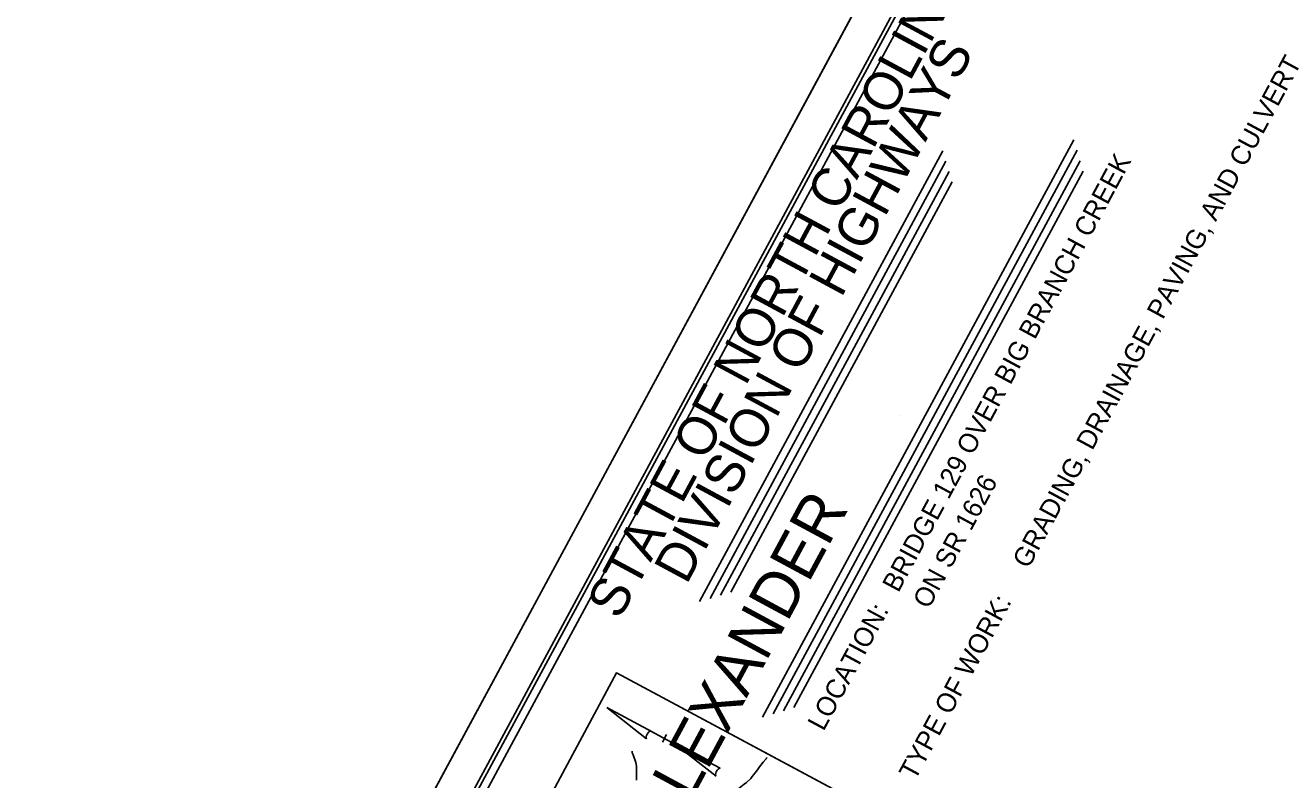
# Model space of a CAD drawing. Extents: x 1376167 to 1379209, y 761324 to 763997.
# Drawn here: x 1376167 to 1376982, y 763015 to 763505 of the extents above; entities that cross this region are included whole.
import ezdxf

# ---------------------------------------------------------------- set-up
doc = ezdxf.new("R2010")
doc.units = 0
for name, color, linetype in [('Default', 7, 'Continuous'), ('Old_Level_1', 7, 'Continuous'), ('Prop North Arrow for Plan Sheets CELL', 7, 'Continuous'), ('Sheet Cutting Line CELL', 7, 'Continuous'), ('Sheet Data Field CELL', 7, 'Continuous'), ('Sheet Plot Border Inside CELL', 7, 'Continuous'), ('Sheet Plot Border Outside CELL', 7, 'Continuous'), ('Sheet Title CELL', 7, 'Continuous'), ('Sheet Title Data Points CELL', 7, 'Continuous')]:
    doc.layers.add(name, color=color, linetype=linetype)

msp = doc.modelspace()

# ---------------------------------------------------------------- linework, layer by layer
at = {"layer": 'Default'}
for points in [[(1376563.93, 763014.38), (1376563.87, 763014.67), (1376563.82, 763014.91), (1376563.89, 763015.39), (1376563.85, 763015.89), (1376563.9, 763016.29), (1376563.89, 763017.05), (1376563.93, 763018.96), (1376563.99, 763020.92), (1376564.01, 763023.25), (1376563.78, 763024.72), (1376563.56, 763025.79), (1376561.67, 763030.75), (1376561.15, 763032.22), (1376561.1, 763032.48), (1376561.08, 763033.15)], [(1376648.76, 763029.08), (1376648.29, 763028.55), (1376648, 763028.24), (1376647.83, 763028.06), (1376646.1, 763025.98), (1376643.79, 763022.92), (1376642.92, 763021.74), (1376641.74, 763020.29), (1376640.75, 763018.98), (1376640.14, 763018.1), (1376639.06, 763016.64), (1376638.1, 763015.54), (1376635.43, 763012.95), (1376633.91, 763011.77), (1376630.52, 763009.14), (1376629.15, 763008.11), (1376628.26, 763007.42), (1376627.71, 763006.98)]]:
    msp.add_lwpolyline(points, dxfattribs=at)
at = {"layer": 'Old_Level_1'}
for points in [[(1376622.61, 762553.05), (1376345.79, 762701.47), (1376550.88, 763083.99), (1376827.7, 762935.57)], [(1376345.79, 762701.47), (1376660.36, 762532.81), (1376865.45, 762915.33), (1376550.88, 763083.99)]]:
    msp.add_lwpolyline(points, close=True, dxfattribs=at)
at = {"layer": 'Prop North Arrow for Plan Sheets CELL'}
for p, q in [((1376544.62, 763061.56), (1376544.6, 763061.53)), ((1376544.62, 763061.56), (1376544.6, 763061.53)), ((1376570.39, 763041.21), (1376544.6, 763061.53)), ((1376544.62, 763061.56), (1376574, 763045.8)), ((1376589.25, 763037.63), (1376573.14, 763046.26)), ((1376574, 763045.8), (1376573.17, 763046.25)), ((1376580.8, 763038.99), (1376580.78, 763038.96)), ((1376581.97, 763041.17), (1376580.8, 763038.99)), ((1376580.81, 763039.02), (1376583.45, 763043.94)), ((1376589.25, 763037.63), (1376615.54, 763016.92)), ((1376618.19, 763022.15), (1376589.25, 763037.63))]:
    msp.add_line(p, q, dxfattribs=at)
for centre, start_param, end_param in [((1376572.06, 763043.59), 0.216388, 2.908219), ((1376617.04, 763019.47), 0.201328, 3.141593)]:
    msp.add_ellipse(centre, major_axis=(1.41, 2.59), ratio=0.461098, start_param=start_param, end_param=end_param, dxfattribs=at)
at = {"layer": 'Sheet Cutting Line CELL'}
msp.add_line((1376166.94, 762515.18), (1376966.07, 763997.49), dxfattribs=at)
at = {"layer": 'Sheet Plot Border Inside CELL'}
msp.add_lwpolyline([(1377121.6, 762015.28), (1377912.43, 763482.18), (1376983.7, 763982.88), (1376192.87, 762515.97)], close=True, dxfattribs=at)
at = {"layer": 'Sheet Plot Border Outside CELL'}
msp.add_lwpolyline([(1376966.07, 763997.49), (1376166.94, 762515.18), (1377135.18, 761993.19), (1377934.31, 763475.5)], close=True, dxfattribs=at)
at = {"layer": 'Sheet Title CELL'}
for p, q in [((1376645.78, 763055.4), (1376847.95, 763430.37)), ((1376604.91, 763130.43), (1376762.8, 763423.34)), ((1376652.56, 763057.43), (1376849.98, 763423.6)), ((1376611.67, 763132.47), (1376764.84, 763416.56)), ((1376659.34, 763059.45), (1376852, 763416.83)), ((1376618.45, 763134.49), (1376766.86, 763409.79)), ((1376666.1, 763061.49), (1376854.03, 763410.05)), ((1376625.23, 763136.52), (1376768.89, 763403.02))]:
    msp.add_line(p, q, dxfattribs=at)
for points in [[(1376975.27, 763961.87), (1376272.92, 762659.12)], [(1376977.29, 763955.09), (1376303.44, 762705.17)]]:
    msp.add_lwpolyline(points, dxfattribs=at)
at = {"layer": 'Sheet Title Data Points CELL'}
for p, q in [((1376839.3, 763331.2), (1376839.3, 763331.2)), ((1376734.48, 763251.32), (1376734.48, 763251.32))]:
    msp.add_line(p, q, dxfattribs=at)

# ---------------------------------------------------------------- texts
at = {"layer": 'Sheet Data Field CELL'}
for s, height, p in [('GRADING, DRAINAGE, PAVING, AND CULVERT', 12.5001, (1376818.41, 763151.22)), ('BRIDGE 129 OVER BIG BRANCH CREEK', 12.5001, (1376733.88, 763135.68)), ('ON SR 1626', 12.5, (1376753.69, 763125.01)), ('          ALEXANDER          ', 30, (1376533.71, 762878.93))]:
    msp.add_text(s, height=height, rotation=61.67024, dxfattribs=at).set_placement(p)
at = {"layer": 'Sheet Title CELL'}
for s, height, p in [('STATE OF NORTH CAROLINA', 24.9999, (1376552.75, 763117.88)), ('DIVISION OF HIGHWAYS', 24.9999, (1376596.36, 763140.84)), ('LOCATION: ', 12.5, (1376685.35, 763045.66)), ('TYPE OF WORK:', 12.5001, (1376744.77, 763013.62))]:
    msp.add_text(s, height=height, rotation=61.67024, dxfattribs=at).set_placement(p)

doc.saveas('drawing.dxf')
